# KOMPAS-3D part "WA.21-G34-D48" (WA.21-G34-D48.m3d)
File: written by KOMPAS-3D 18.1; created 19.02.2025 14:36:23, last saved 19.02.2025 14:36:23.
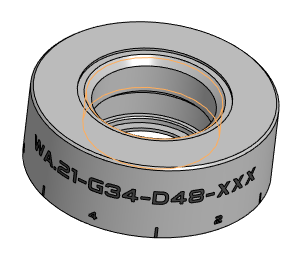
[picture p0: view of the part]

Document properties: Автор: user; Полное имя файла: Z:\Элхарт\БД\3D модели\ЭЛХАРТ\PTE1000M\WA.21-G34-D48.m3d

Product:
- Part/product: WA.21-G34-D48

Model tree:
1. Операция без истории:1  (labels: WA.21-G34-D48)
2. Условное изображение резьбы:1  (with: Операция без истории:1)
     Длина резьбы = 7.55895; Шаг резьбы = 1.814; Номинальный диаметр резьбы = 26.441
3. Подгонка:1  (with: Операция без истории:1)

Expressions: G 3/4; cil2_6357-81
